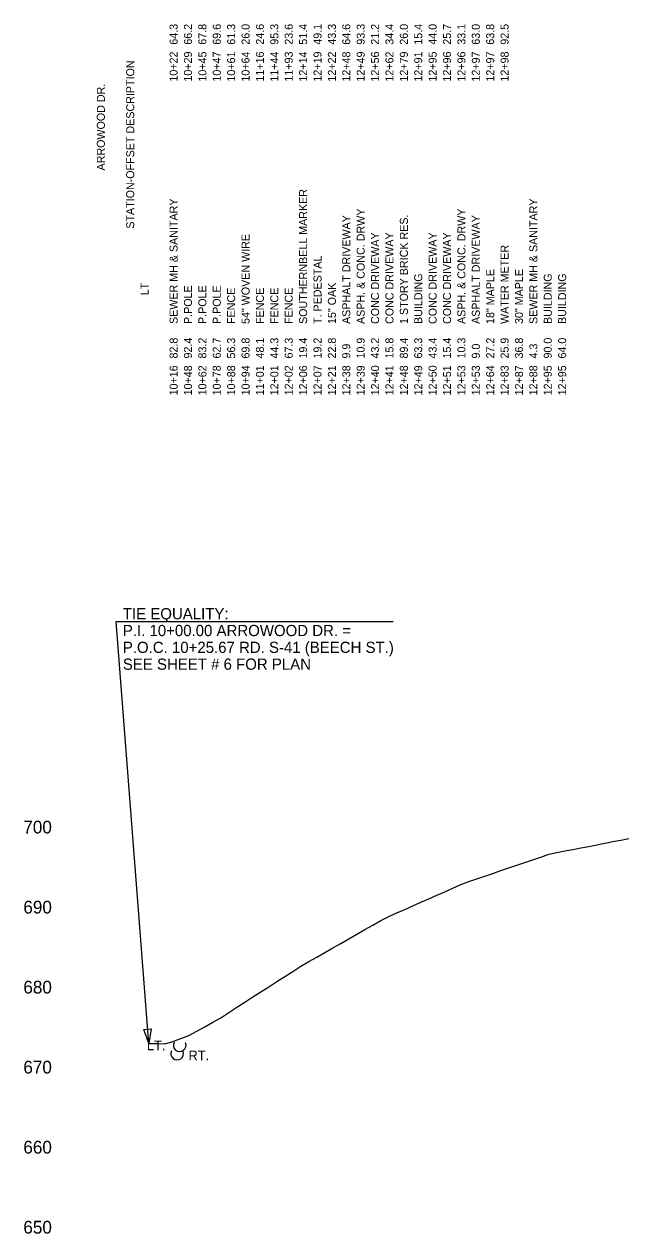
# Model space of a CAD drawing. Extents: x 16382402 to 16388022, y 46194326 to 46202918.
# Drawn here: x 16384274 to 16384651, y 46196922 to 46197677 of the extents above; entities that cross this region are included whole.
import ezdxf

# ---------------------------------------------------------------- set-up
doc = ezdxf.new("R2010")
doc.units = 0
for name, color, linetype in [('Default', 7, 'Continuous'), ('RD_DDB_ElevTX', 7, 'Continuous'), ('RD_DDB_Profile_EX', 7, 'Continuous'), ('RD_HC_Data', 7, 'Continuous'), ('RD_TX_Bldg', 7, 'Continuous'), ('RD_TX_Drainage', 7, 'Continuous')]:
    doc.layers.add(name, color=color, linetype=linetype)

msp = doc.modelspace()

# ---------------------------------------------------------------- linework, layer by layer
at = {"layer": 'Default'}
for centre in [(16384370.75, 46197039.57), (16384369.15, 46197034.32)]:
    msp.add_arc(centre, 3.98, 153.82804, 22.53319, dxfattribs=at)
at = {"layer": 'RD_DDB_Profile_EX'}
msp.add_lwpolyline([(16384351.35, 46197040.64), (16384356.35, 46197040.51), (16384361.35, 46197040.34), (16384366.35, 46197041.87), (16384371.35, 46197043.65), (16384376.35, 46197045.68), (16384381.35, 46197048.23), (16384386.35, 46197051.02), (16384391.35, 46197053.86), (16384396.35, 46197056.69), (16384401.35, 46197060.01), (16384406.35, 46197063.26), (16384411.35, 46197066.48), (16384416.35, 46197069.66), (16384421.35, 46197072.84), (16384426.35, 46197076.04), (16384431.35, 46197079.29), (16384436.35, 46197082.48), (16384441.35, 46197085.66), (16384446.35, 46197088.84), (16384451.35, 46197091.75), (16384456.35, 46197094.58), (16384461.35, 46197097.44), (16384466.35, 46197100.31), (16384471.35, 46197103.17), (16384476.35, 46197105.99), (16384481.35, 46197108.86), (16384486.35, 46197111.73), (16384491.35, 46197114.6), (16384496.35, 46197117.47), (16384501.35, 46197119.97), (16384506.35, 46197122.18), (16384511.35, 46197124.39), (16384516.35, 46197126.59), (16384521.35, 46197128.8), (16384526.35, 46197131.01), (16384531.35, 46197133.22), (16384536.35, 46197135.42), (16384541.35, 46197137.63), (16384546.35, 46197139.84), (16384551.35, 46197141.82), (16384556.35, 46197143.52), (16384561.35, 46197145.21), (16384566.35, 46197146.9), (16384571.35, 46197148.59), (16384576.35, 46197150.29), (16384581.35, 46197151.99), (16384586.35, 46197153.68), (16384591.35, 46197155.37), (16384596.35, 46197157.07), (16384601.35, 46197158.79), (16384606.35, 46197159.88), (16384611.35, 46197160.88), (16384616.35, 46197161.87), (16384621.35, 46197162.86), (16384626.35, 46197163.78), (16384631.35, 46197164.76), (16384636.35, 46197165.76), (16384641.35, 46197166.75), (16384646.35, 46197167.72), (16384651.35, 46197168.63)], dxfattribs=at)
at = {"layer": 'RD_HC_Data'}
for p, q in [((16384331.02, 46197304.2), (16384504.19, 46197304.2)), ((16384351.35, 46197040.64), (16384331.02, 46197304.2))]:
    msp.add_line(p, q, dxfattribs=at)
at = {"layer": 'RD_TX_Drainage'}
msp.add_lwpolyline([(16384352.9, 46197049.79), (16384351.35, 46197040.64), (16384348.41, 46197049.44)], close=True, dxfattribs=at)

# ---------------------------------------------------------------- texts
at = {"layer": 'Default'}
for s, p in [('LT.', (16384350.22, 46197036.41)), ('RT.', (16384376.23, 46197030.11))]:
    msp.add_text(s, height=6, dxfattribs=at).set_placement(p)
at = {"layer": 'RD_DDB_ElevTX'}
for s, p in [('700', (16384273.02, 46197171.8)), ('690', (16384273.02, 46197121.8)), ('680', (16384273.02, 46197071.8)), ('670', (16384273.02, 46197021.8)), ('660', (16384273.02, 46196971.8)), ('650', (16384273.02, 46196921.8))]:
    msp.add_text(s, height=8, dxfattribs=at).set_placement(p)
at = {"layer": 'RD_HC_Data'}
for s, p in [('TIE EQUALITY:', (16384335.21, 46197305.62)), ('P.I. 10+00.00 ARROWOOD DR. =', (16384335.21, 46197295.12)), ('P.O.C. 10+25.67 RD. S-41 (BEECH ST.)', (16384335.21, 46197284.62)), ('SEE SHEET # 6 FOR PLAN', (16384335.21, 46197274.12))]:
    msp.add_text(s, height=7, dxfattribs=at).set_placement(p)
at = {"layer": 'RD_TX_Bldg'}
for s, p in [('64.3', (16384369.42, 46197664.65)), ('66.2', (16384378.41, 46197664.65)), ('67.8', (16384387.4, 46197664.65)), ('69.6', (16384396.39, 46197664.65)), ('61.3', (16384405.39, 46197664.65)), ('26.0', (16384414.38, 46197664.65)), ('24.6', (16384423.37, 46197664.65)), ('95.3', (16384432.36, 46197664.65)), ('23.6', (16384441.35, 46197664.65)), ('51.4', (16384450.34, 46197664.65)), ('49.1', (16384459.34, 46197664.65)), ('43.3', (16384468.33, 46197664.65)), ('64.6', (16384477.32, 46197664.65)), ('93.3', (16384486.31, 46197664.65)), ('21.2', (16384495.3, 46197664.65)), ('34.4', (16384504.29, 46197664.65)), ('26.0', (16384513.29, 46197664.65)), ('15.4', (16384522.28, 46197664.65)), ('44.0', (16384531.27, 46197664.65)), ('25.7', (16384540.26, 46197664.65)), ('33.1', (16384549.25, 46197664.65)), ('63.0', (16384558.25, 46197664.65)), ('63.8', (16384567.24, 46197664.65)), ('92.5', (16384576.23, 46197664.65)), ('10+22', (16384369.42, 46197641.6)), ('10+29', (16384378.41, 46197641.6)), ('10+45', (16384387.4, 46197641.6)), ('10+47', (16384396.39, 46197641.6)), ('10+61', (16384405.39, 46197641.6)), ('10+64', (16384414.38, 46197641.6)), ('11+16', (16384423.37, 46197641.6)), ('11+44', (16384432.36, 46197641.6)), ('11+93', (16384441.35, 46197641.6)), ('12+14', (16384450.34, 46197641.6)), ('12+19', (16384459.34, 46197641.6)), ('12+22', (16384468.33, 46197641.6)), ('12+48', (16384477.32, 46197641.6)), ('12+49', (16384486.31, 46197641.6)), ('12+56', (16384495.3, 46197641.6)), ('12+62', (16384504.29, 46197641.6)), ('12+79', (16384513.29, 46197641.6)), ('12+91', (16384522.28, 46197641.6)), ('12+95', (16384531.27, 46197641.6)), ('12+96', (16384540.26, 46197641.6)), ('12+96', (16384549.25, 46197641.6)), ('12+97', (16384558.25, 46197641.6)), ('12+97', (16384567.24, 46197641.6)), ('12+98', (16384576.23, 46197641.6)), ('STATION-OFFSET DESCRIPTION', (16384342.32, 46197549.7)), ('ARROWOOD DR.', (16384323.96, 46197586.05)), ('SEWER MH & SANITARY', (16384369.42, 46197490.16)), ('SOUTHERNBELL MARKER', (16384450.34, 46197490.16)), ('SEWER MH & SANITARY', (16384594.21, 46197490.16)), ('ASPH. & CONC. DRWY', (16384486.31, 46197490.16)), ('ASPH. & CONC. DRWY', (16384549.25, 46197490.16)), ('ASPHALT DRIVEWAY', (16384477.32, 46197490.16)), ('1 STORY BRICK RES.', (16384513.29, 46197490.16)), ('ASPHALT DRIVEWAY', (16384558.25, 46197490.16)), ('54" WOVEN WIRE', (16384414.38, 46197490.16)), ('CONC DRIVEWAY', (16384495.3, 46197490.16)), ('CONC DRIVEWAY', (16384504.29, 46197490.16)), ('CONC DRIVEWAY', (16384531.27, 46197490.16)), ('CONC DRIVEWAY', (16384540.26, 46197490.16)), ('WATER METER', (16384576.23, 46197490.16)), ('T. PEDESTAL', (16384459.34, 46197490.16)), ('18" MAPLE', (16384567.24, 46197490.16)), ('30" MAPLE', (16384585.22, 46197490.16)), ('LT', (16384351.31, 46197508.1)), ('15" OAK', (16384468.33, 46197490.16)), ('BUILDING', (16384522.28, 46197490.16)), ('BUILDING', (16384603.2, 46197490.16)), ('BUILDING', (16384612.2, 46197490.16)), ('P.POLE', (16384378.41, 46197490.16)), ('P.POLE', (16384387.4, 46197490.16)), ('P.POLE', (16384396.39, 46197490.16)), ('FENCE', (16384405.39, 46197490.16)), ('FENCE', (16384423.37, 46197490.16)), ('FENCE', (16384432.36, 46197490.16)), ('FENCE', (16384441.35, 46197490.16)), ('82.8', (16384369.42, 46197468.58)), ('92.4', (16384378.41, 46197468.58)), ('83.2', (16384387.4, 46197468.58)), ('62.7', (16384396.39, 46197468.58)), ('56.3', (16384405.39, 46197468.58)), ('69.8', (16384414.38, 46197468.58)), ('48.1', (16384423.37, 46197468.58)), ('44.3', (16384432.36, 46197468.58)), ('67.3', (16384441.35, 46197468.58)), ('19.4', (16384450.34, 46197468.58)), ('19.2', (16384459.34, 46197468.58)), ('22.8', (16384468.33, 46197468.58)), ('9.9', (16384477.32, 46197468.58)), ('10.9', (16384486.31, 46197468.58)), ('43.2', (16384495.3, 46197468.58)), ('15.8', (16384504.29, 46197468.58)), ('89.4', (16384513.29, 46197468.58)), ('63.3', (16384522.28, 46197468.58)), ('43.4', (16384531.27, 46197468.58)), ('15.4', (16384540.26, 46197468.58)), ('10.3', (16384549.25, 46197468.58)), ('9.0', (16384558.25, 46197468.58)), ('27.2', (16384567.24, 46197468.58)), ('25.9', (16384576.23, 46197468.58)), ('36.8', (16384585.22, 46197468.58)), ('4.3', (16384594.21, 46197468.58)), ('90.0', (16384603.2, 46197468.58)), ('64.0', (16384612.2, 46197468.58)), ('10+16', (16384369.42, 46197445.53)), ('10+48', (16384378.41, 46197445.53)), ('10+62', (16384387.4, 46197445.53)), ('10+78', (16384396.39, 46197445.53)), ('10+88', (16384405.39, 46197445.53)), ('10+94', (16384414.38, 46197445.53)), ('11+01', (16384423.37, 46197445.53)), ('12+01', (16384432.36, 46197445.53)), ('12+02', (16384441.35, 46197445.53)), ('12+06', (16384450.34, 46197445.53)), ('12+07', (16384459.34, 46197445.53)), ('12+21', (16384468.33, 46197445.53)), ('12+38', (16384477.32, 46197445.53)), ('12+39', (16384486.31, 46197445.53)), ('12+40', (16384495.3, 46197445.53)), ('12+41', (16384504.29, 46197445.53)), ('12+48', (16384513.29, 46197445.53)), ('12+49', (16384522.28, 46197445.53)), ('12+50', (16384531.27, 46197445.53)), ('12+51', (16384540.26, 46197445.53)), ('12+53', (16384549.25, 46197445.53)), ('12+53', (16384558.25, 46197445.53)), ('12+64', (16384567.24, 46197445.53)), ('12+83', (16384576.23, 46197445.53)), ('12+87', (16384585.22, 46197445.53)), ('12+88', (16384594.21, 46197445.53)), ('12+95', (16384603.2, 46197445.53)), ('12+95', (16384612.2, 46197445.53))]:
    msp.add_text(s, height=5, rotation=90, dxfattribs=at).set_placement(p)

doc.saveas('drawing.dxf')
